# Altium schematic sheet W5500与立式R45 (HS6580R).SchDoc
size 304 x 182 mm; SheetNumber: 0; SheetTotal: 0
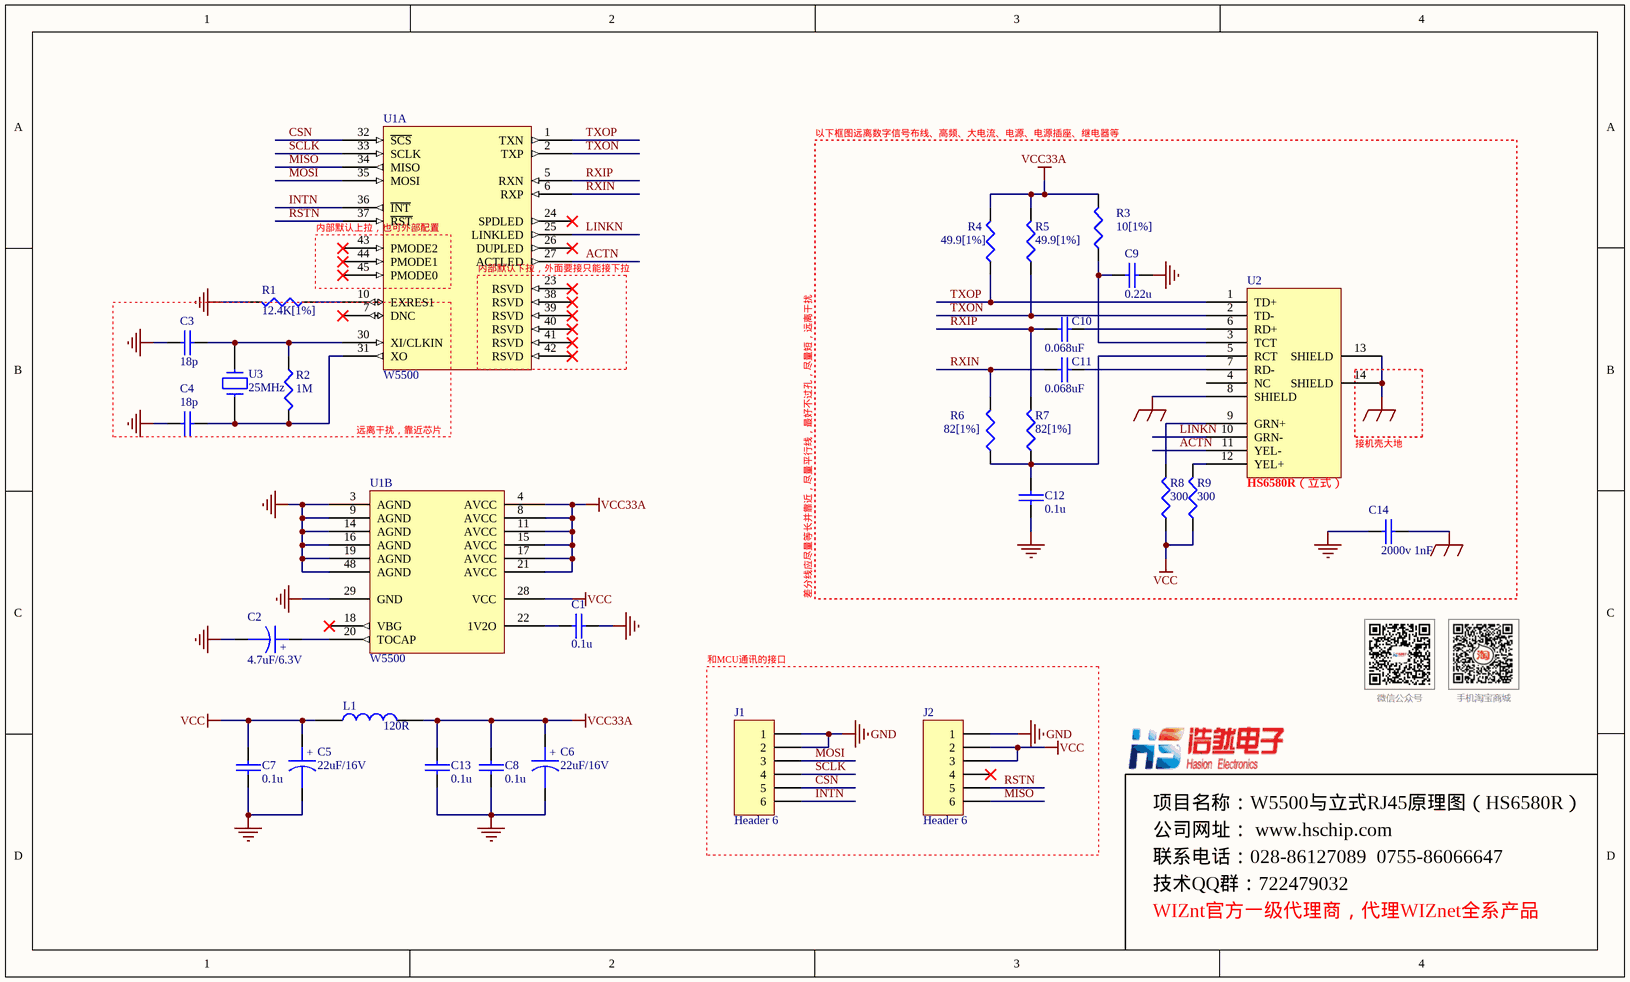
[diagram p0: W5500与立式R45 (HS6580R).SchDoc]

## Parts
C1  0.1u  [0603]
C2  4.7uF/6.3V  [3216]
C3  18p  [0603]
C4  18p  [0603]
C5  22uF/16V  [3216]
C6  22uF/16V  [3216]
C7  0.1u  [0603]
C8  0.1u  [0603]
C9  0.22u  [0603]
C10  0.068uF  [0603]
C11  0.068uF  [0603]
C12  0.1u  [0603]
C13  0.1u  [0603]
C14  2000v 1nF  [3216]
J1  Header 6  [SIP6]
J2  Header 6  [SIP6]
L1  120R  [0603]
R1  12.4K[1%]  [0603]
R2  1M  [0603]
R3  10[1%]  [0603]
R4  49.9[1%]  [0603]
R5  49.9[1%]  [0603]
R6  82[1%]  [0603]
R7  82[1%]  [0603]
R8  300  [0603]
R9  300  [0603]
U1  W5500  [LQFP48-W5500/W5100S/W6100/C8T6]  (parts A,B of 2)
U2  HS6580R（立式）  [RJ45-HS6580R]
U3  25MHz  [XTAL-49S]

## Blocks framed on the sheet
远离干扰，靠近芯片: C3 C4 R2 U3
和MCU通讯的接口: J1 J2

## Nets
EARTH: C14.1 U2.8(SHIELD) U2.13(SHIELD) U2.14(SHIELD)
GND: C1.1 C2.2 C3.2 C4.2 C5.2 C6.2 C7.2 C8.2 C9.2 C12.1 C13.2 C14.2 J1.1 J1.2 J2.1 R1.2 U1.3(AGND) U1.9(AGND) U1.14(AGND) U1.16(AGND) U1.19(AGND) U1.29(GND) U1.48(AGND)
VCC: C5.1 C7.1 J2.2 J2.3 L1.1 R8.1 R9.1 U1.28(VCC)
VCC33A: C6.1 C8.1 C13.1 L1.2 R3.2 R4.2 R5.2 U1.4(AVCC) U1.8(AVCC) U1.11(AVCC) U1.15(AVCC) U1.17(AVCC) U1.21(AVCC)
ACTN: U1.27(ACTLED) U2.11(YEL-)
CSN: J1.5 U1.32(~{SCS})
INTN: J1.6 U1.36(~{INT})
LINKN: U1.25(LINKLED) U2.10(GRN-)
MISO: J2.6 U1.34(MISO)
MOSI: J1.3 U1.35(MOSI)
RSTN: J2.5 U1.37(~{RST})
RXIN: C11.1 R6.2 U1.6(RXP)
RXIP: C10.1 R7.2 U1.5(RXN)
SCLK: J1.4 U1.33(SCLK)
TXON: R5.1 U1.2(TXP) U2.2(TD-)
TXOP: R4.1 U1.1(TXN) U2.1(TD+)
NetC1_2: C1.2 U1.22(1V2O)
NetC2_1: C2.1 U1.20(TOCAP)
NetC3_1: C3.1 R2.1 U1.30(XI/CLKIN) U3.1
NetC4_1: C4.1 R2.2 U1.31(XO) U3.2
NetC9_1: C9.1 R3.1 U2.3(TCT)
NetC10_2: C10.2 U2.6(RD+)
NetC11_2: C11.2 U2.7(RD-)
NetC12_2: C12.2 R6.1 R7.1 U2.5(RCT)
NetR1_1: R1.1 U1.10(EXRES1)
NetR8_2: R8.2 U2.9(GRN+)
NetR9_2: R9.2 U2.12(YEL+)

Not connected (* = marked no-connect by the designer): J2 4*; U1 7(DNC)* 18(VBG)* 23(RSVD)* 24(SPDLED)* 26(DUPLED)* 38(RSVD)* 39(RSVD)* 40(RSVD)* 41(RSVD)* 42(RSVD)* 43(PMODE2)* 44(PMODE1)* 45(PMODE0)*; U2 4(NC)

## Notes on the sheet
- 以下框图远离数字信号布线、高频、大电流、电源、电源插座、继电器等
- (near U1) 内部默认上拉，也可外部配置
- (near U1) 内部默认下拉，外面要接只能接下拉
- (near U2) 接机壳大地
- 差分线应尽量等长并靠近，尽量平行线，最好不过孔，尽量短，远离干扰
- 项目名称：W5500与立式RJ45原理图（HS6580R）
- 公司网址： www.hschip.com
- 联系电话：028-86127089  0755-86066647
- WIZnt官方一级代理商，代理WIZnet全系产品
- 技术QQ群：722479032

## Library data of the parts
C1 C3 C4 C7-C14 = CAP: Capacitor
C2 C5 C6 = CAPACITOR POL: Capacitor
J1 J2 = Header 6: Header, 6-Pin
L1 = INDUCTOR
R1-R9 = RES1
U2 = HS6580R
U3 = CRYSTAL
